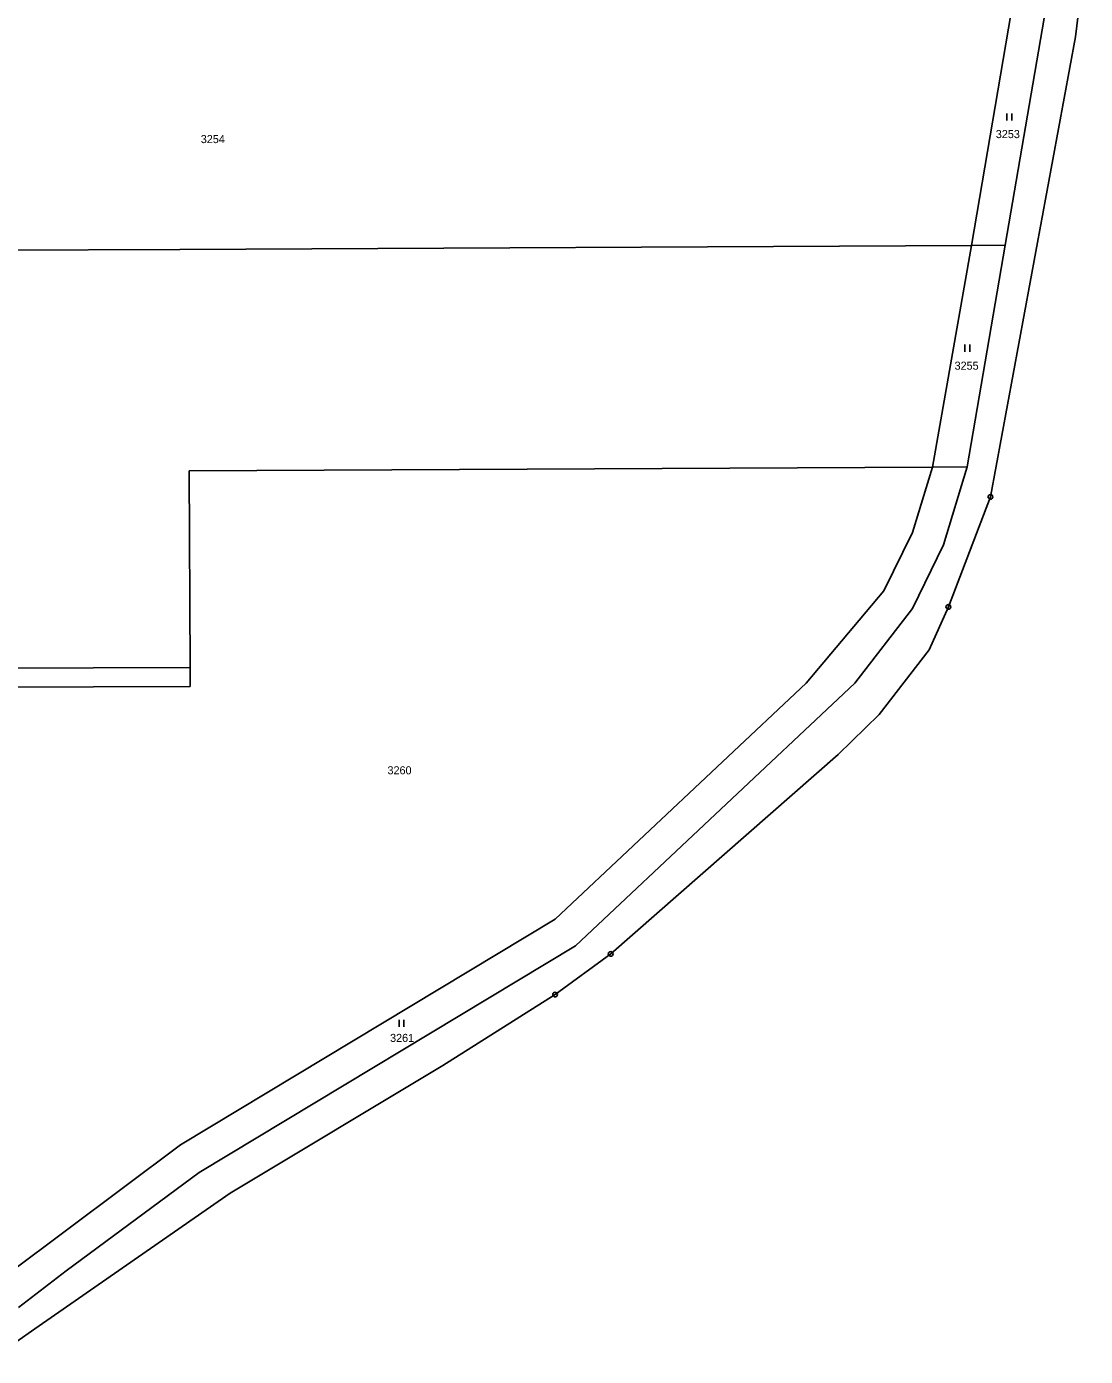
# Model space of a CAD drawing. Extents: x -618848 to -615803, y -1044450 to -1042254.
# Drawn here: x -617212.5 to -616989.8, y -1044273.7 to -1043993.9 of the extents above; entities that cross this region are included whole.
import ezdxf

# ---------------------------------------------------------------- set-up
doc = ezdxf.new("R2010")
doc.units = 0
doc.header["$LTSCALE"] = 0.68
for name, color, linetype, lineweight in [('1', 7, 'Continuous', 25), ('3', 7, 'Continuous', 25), ('8', 7, 'Continuous', 25)]:
    doc.layers.add(name, color=color, linetype=linetype, lineweight=lineweight)
doc.layers.add('2', color=7, linetype='Continuous')

msp = doc.modelspace()

# ---------------------------------------------------------------- linework, layer by layer
at = {"layer": '1'}
for p, q in [((-617013.77, -1044039.95), (-617004.69, -1043986.79)), ((-616997.58, -1043986.75), (-617006.66, -1044039.91)), ((-617180.26, -1044040.77), (-617013.77, -1044039.95)), ((-617021.96, -1044086.57), (-617013.77, -1044039.95)), ((-617006.66, -1044039.91), (-617014.63, -1044086.53)), ((-617006.66, -1044039.91), (-617013.77, -1044039.95)), ((-617346.74, -1044041.59), (-617180.26, -1044040.77)), ((-617178.28, -1044087.34), (-617021.96, -1044086.57)), ((-617178.08, -1044128.73), (-617178.28, -1044087.34)), ((-617026.19, -1044100.35), (-617021.96, -1044086.57)), ((-617014.63, -1044086.53), (-617021.96, -1044086.57)), ((-617014.63, -1044086.53), (-617019.66, -1044102.93)), ((-617018.62, -1044116.01), (-617009.77, -1044092.86)), ((-617032.16, -1044112.62), (-617026.19, -1044100.35)), ((-617019.66, -1044102.93), (-617026.18, -1044116.32)), ((-617048.54, -1044132.09), (-617032.16, -1044112.62)), ((-617026.18, -1044116.32), (-617038.27, -1044132.04)), ((-617022.67, -1044125.06), (-617018.62, -1044116.01)), ((-617033.19, -1044138.65), (-617022.67, -1044125.06)), ((-617178.08, -1044128.73), (-617302.68, -1044129.34)), ((-617178.06, -1044132.73), (-617178.08, -1044128.73)), ((-617101.31, -1044181.73), (-617048.54, -1044132.09)), ((-617038.27, -1044132.04), (-617097.06, -1044187.34)), ((-617247.69, -1044133.08), (-617178.06, -1044132.73)), ((-617041.77, -1044147.05), (-617033.19, -1044138.65)), ((-617089.64, -1044189.03), (-617041.77, -1044147.05)), ((-617180.13, -1044229.25), (-617101.31, -1044181.73)), ((-617097.06, -1044187.34), (-617176.22, -1044235.06)), ((-617101.34, -1044197.59), (-617089.64, -1044189.03)), ((-617124.92, -1044212.51), (-617101.34, -1044197.59)), ((-617169.64, -1044239.37), (-617124.92, -1044212.51)), ((-617216.07, -1044256.12), (-617180.13, -1044229.25)), ((-617176.22, -1044235.06), (-617204.19, -1044255.72)), ((-617210.78, -1044267.96), (-617169.64, -1044239.37)), ((-617204.19, -1044255.72), (-617214.19, -1044263.45)), ((-617219.1, -1044273.74), (-617210.78, -1044267.96))]:
    msp.add_line(p, q, dxfattribs=at)
msp.add_lwpolyline([(-617009.77, -1044092.86), (-616991.88, -1043996.06), (-616989.8, -1043978.54)], dxfattribs=at)
at = {"layer": '3'}
for p, q in [((-617006.301, -1044013.67), (-617006.301, -1044012.17)), ((-617005.3, -1044013.67), (-617005.3, -1044012.17)), ((-617015.121, -1044062.32), (-617015.121, -1044060.82)), ((-617014.12, -1044062.32), (-617014.12, -1044060.82)), ((-617134.151, -1044204.4), (-617134.151, -1044202.9)), ((-617133.15, -1044204.4), (-617133.15, -1044202.9))]:
    msp.add_line(p, q, dxfattribs=at)
at = {"layer": '8'}
for centre, radius in [((-617009.77, -1044092.8599), 0.5), ((-617009.77, -1044092.8599), 0.0303), ((-617018.62, -1044116.0099), 0.5), ((-617018.62, -1044116.0099), 0.0303), ((-617089.64, -1044189.0299), 0.5), ((-617089.64, -1044189.0299), 0.0303), ((-617101.34, -1044197.5899), 0.5), ((-617101.34, -1044197.5899), 0.0303)]:
    msp.add_circle(centre, radius, dxfattribs=at)

# ---------------------------------------------------------------- texts
at = {"layer": '2'}
for s, p in [('3254', (-617175.85, -1044018.405)), ('3253', (-617008.64, -1044017.355)), ('3255', (-617017.31, -1044066.095)), ('3260', (-617136.58, -1044151.245)), ('3261', (-617136.04, -1044207.565))]:
    msp.add_text(s, height=1.7, dxfattribs=at).set_placement(p)

doc.saveas('drawing.dxf')
